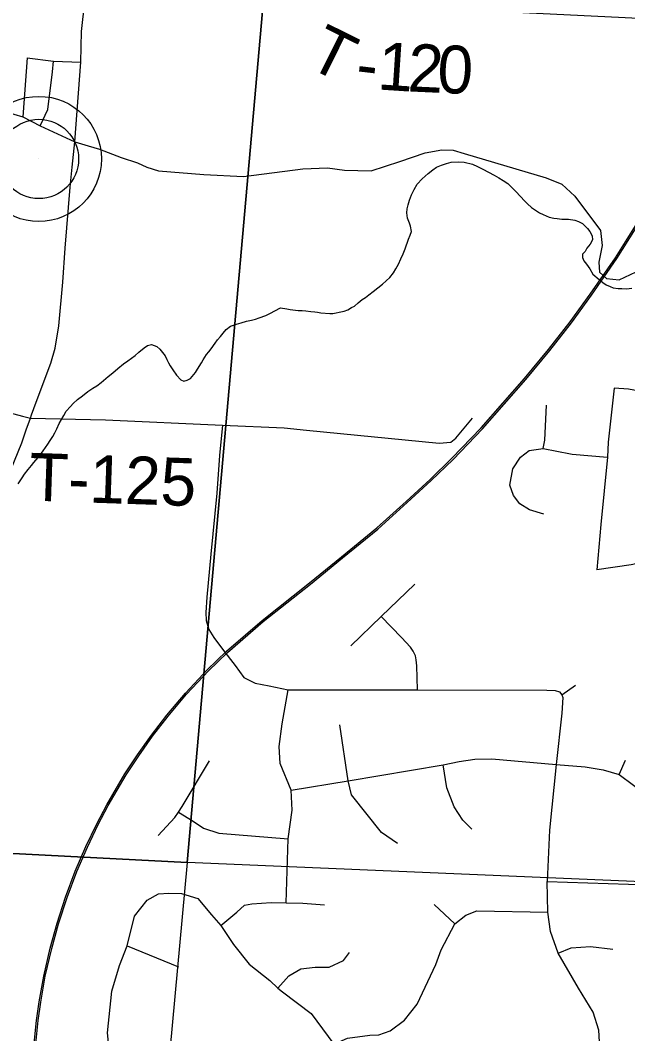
# Model space of a CAD drawing. Extents: x 0 to 34, y 0 to 22.
# Drawn here: x 7.317 to 8.039, y 15.851 to 17.056 of the extents above; entities that cross this region are included whole.
import ezdxf

# ---------------------------------------------------------------- set-up
doc = ezdxf.new("R2010")
doc.units = 0
for name, color, linetype in [('GM_X_County_Road', 7, 'Continuous'), ('GM_X_Minor_River', 7, 'Continuous'), ('GM_X_Rail_Line', 7, 'Continuous'), ('GM_X_Section', 7, 'Continuous'), ('GM_X_Township_Road', 7, 'Continuous'), ('GM_X_Township_Road_Text', 7, 'Continuous'), ('GM_X_Unincorporated', 7, 'Continuous'), ('GM_X_Unincorporated_Location', 7, 'Continuous')]:
    doc.layers.add(name, color=color, linetype=linetype)

msp = doc.modelspace()

# ---------------------------------------------------------------- linework, layer by layer
at = {"layer": 'GM_X_County_Road'}
msp.add_line((7.379, 16.8818), (7.382, 16.9119), dxfattribs=at)
for points in [[(7.382, 16.9119), (7.3892, 17.0066), (7.3899, 17.0431), (7.3983, 17.1175), (7.4035, 17.1411), (7.4162, 17.1655), (7.4386, 17.1904), (7.4667, 17.2146), (7.5042, 17.2448), (7.528, 17.2611), (7.5783, 17.3081), (7.6505, 17.3755), (7.733, 17.4723), (7.8521, 17.6108), (7.8757, 17.6392), (7.9049, 17.673), (7.9181, 17.6858), (7.9702, 17.7222), (8.0096, 17.7756), (8.0113, 17.7781)], [(6.7693, 17.1094), (6.8344, 17.0818), (6.9097, 17.0436), (6.9449, 17.0241), (6.9833, 17.0009), (7.0435, 16.9721), (7.0866, 16.9621), (7.0965, 16.9604), (7.1364, 16.9551), (7.2991, 16.9477), (7.3202, 16.9415), (7.341, 16.9307), (7.382, 16.9119)], [(7.3243, 16.5692), (7.3293, 16.5833), (7.3307, 16.5871), (7.3363, 16.6021), (7.3536, 16.6484), (7.3587, 16.6664), (7.3633, 16.693), (7.3678, 16.745), (7.3705, 16.7852), (7.3767, 16.8577), (7.379, 16.8818)], [(7.2846, 16.4559), (7.2861, 16.4596), (7.3061, 16.5217), (7.319, 16.554), (7.3243, 16.5692)]]:
    msp.add_lwpolyline(points, dxfattribs=at)
at = {"layer": 'GM_X_Minor_River'}
for points in [[(7.7799, 16.8426), (7.7824, 16.8486), (7.7856, 16.855), (7.7892, 16.8613), (7.7951, 16.8676), (7.8021, 16.8742), (7.8076, 16.8783), (7.8122, 16.8815), (7.818, 16.884), (7.8238, 16.8861), (7.8295, 16.8875), (7.8383, 16.888), (7.8451, 16.8874), (7.8549, 16.8852), (7.8609, 16.8823), (7.8673, 16.8791), (7.874, 16.8755), (7.8804, 16.8722), (7.886, 16.869), (7.8912, 16.8658), (7.8968, 16.8622), (7.9064, 16.8528), (7.9119, 16.8469), (7.9167, 16.8415), (7.9204, 16.8379), (7.9249, 16.8336), (7.9308, 16.8296), (7.9346, 16.8272), (7.9387, 16.8252), (7.9424, 16.8236), (7.9458, 16.8223), (7.9515, 16.821), (7.9553, 16.8205), (7.9609, 16.82), (7.9689, 16.8197), (7.9765, 16.8187), (7.981, 16.8171), (7.9855, 16.8147), (7.9914, 16.8088), (7.9943, 16.8053), (7.9972, 16.7999), (7.9975, 16.7953), (7.9947, 16.79), (7.9907, 16.7852), (7.9887, 16.7815), (7.9856, 16.7782), (7.9855, 16.7744), (7.9872, 16.7701), (7.9905, 16.7662), (7.9942, 16.7608), (7.9978, 16.7546), (8.0056, 16.7479), (8.0097, 16.7447), (8.0138, 16.7419), (8.0183, 16.7399), (8.022, 16.7383), (8.0281, 16.7373), (8.0323, 16.7372), (8.038, 16.737), (8.0444, 16.7376)], [(7.3559, 16.5613), (7.3583, 16.5658), (7.3607, 16.5707), (7.3636, 16.5767), (7.3692, 16.5864), (7.372, 16.5916), (7.3771, 16.5972), (7.3802, 16.6005), (7.3853, 16.6053), (7.3911, 16.6097), (7.3977, 16.6148), (7.4036, 16.6188), (7.4082, 16.6217), (7.4136, 16.6257), (7.4218, 16.6327), (7.4273, 16.6371), (7.4331, 16.6422), (7.4398, 16.6477), (7.4452, 16.6514), (7.4537, 16.6579), (7.4584, 16.6616), (7.4646, 16.6667), (7.4685, 16.6697), (7.4731, 16.6707), (7.4795, 16.6686), (7.4832, 16.6654), (7.4865, 16.6611), (7.4894, 16.6572), (7.4916, 16.653), (7.4934, 16.6491), (7.4956, 16.6456), (7.4985, 16.6406), (7.5028, 16.6344), (7.508, 16.6289), (7.5118, 16.6273), (7.5156, 16.6283), (7.5198, 16.6305), (7.5254, 16.6375), (7.5281, 16.6416), (7.5329, 16.6491), (7.5345, 16.6524), (7.5385, 16.6588), (7.5413, 16.6621), (7.544, 16.6658), (7.5488, 16.6725), (7.5516, 16.6762), (7.5551, 16.6803), (7.5583, 16.6844), (7.5622, 16.6888), (7.5673, 16.6925), (7.5745, 16.6949), (7.5799, 16.6967), (7.586, 16.6984), (7.5922, 16.6997), (7.5968, 16.7011), (7.6014, 16.7025), (7.6091, 16.7053), (7.6148, 16.7081), (7.6199, 16.711), (7.6268, 16.7142), (7.634, 16.7133), (7.6381, 16.7124), (7.6476, 16.7113), (7.6522, 16.7112), (7.6567, 16.7107), (7.6628, 16.7101), (7.6673, 16.7096), (7.6707, 16.7091), (7.6745, 16.7086), (7.6851, 16.7075), (7.6889, 16.7078), (7.6928, 16.7084), (7.6962, 16.7091), (7.7023, 16.7104), (7.7066, 16.7122), (7.7112, 16.7147), (7.7147, 16.7165), (7.719, 16.7202), (7.7236, 16.7242), (7.7275, 16.7267), (7.7318, 16.73), (7.7368, 16.7337), (7.7477, 16.7425), (7.7524, 16.7465), (7.7567, 16.7506), (7.7611, 16.7561), (7.7638, 16.7606), (7.7667, 16.7662), (7.7695, 16.7726), (7.7724, 16.7786), (7.7748, 16.7846), (7.7789, 16.7959), (7.7806, 16.8008), (7.7823, 16.8053), (7.7813, 16.8114), (7.7799, 16.8149), (7.7774, 16.821), (7.7768, 16.8275), (7.7773, 16.832), (7.7782, 16.837), (7.7799, 16.8426)], [(7.3147, 16.5052), (7.3195, 16.5123), (7.3223, 16.5167), (7.3266, 16.5223), (7.3306, 16.5271), (7.3333, 16.5305), (7.3384, 16.5364), (7.3412, 16.5401), (7.3444, 16.5442), (7.3499, 16.5524), (7.3527, 16.5565), (7.3559, 16.5613)]]:
    msp.add_lwpolyline(points, dxfattribs=at)
at = {"layer": 'GM_X_Rail_Line'}
for points in [[(7.333, 15.8316), (7.3366, 15.8672), (7.3399, 15.8893), (7.3451, 15.9199), (7.3528, 15.9531), (7.361, 15.9826), (7.371, 16.0138), (7.3827, 16.0447), (7.3953, 16.074), (7.4083, 16.101), (7.4202, 16.1236), (7.4415, 16.1602), (7.4566, 16.183), (7.4731, 16.2062), (7.4915, 16.23), (7.5136, 16.2562), (7.5396, 16.284), (7.5624, 16.3061), (7.605, 16.3428), (7.6609, 16.3875), (7.6992, 16.4185), (7.7412, 16.4529), (7.776, 16.4842), (7.8045, 16.5104), (7.8303, 16.5356), (7.8653, 16.5719), (7.9168, 16.6303), (7.9453, 16.6649), (7.9709, 16.6978), (7.9948, 16.7306), (8.0247, 16.774), (8.0625, 16.834)], [(7.3349, 15.8314), (7.3385, 15.8669), (7.3418, 15.889), (7.347, 15.9196), (7.3547, 15.9526), (7.3628, 15.982), (7.3729, 16.0131), (7.3845, 16.044), (7.397, 16.0732), (7.41, 16.1001), (7.4219, 16.1226), (7.4432, 16.1591), (7.4582, 16.1819), (7.4746, 16.205), (7.493, 16.2288), (7.515, 16.255), (7.541, 16.2827), (7.5637, 16.3047), (7.6062, 16.3413), (7.6622, 16.386), (7.7004, 16.417), (7.7424, 16.4514), (7.7773, 16.4828), (7.8058, 16.509), (7.8317, 16.5342), (7.8667, 16.5706), (7.9183, 16.6291), (7.9468, 16.6637), (7.9724, 16.6966), (7.9964, 16.7295), (8.0263, 16.7729), (8.0641, 16.833)]]:
    msp.add_lwpolyline(points, dxfattribs=at)
at = {"layer": 'GM_X_Section'}
for points in [[(6.5225, 16.4145), (6.585, 17.1294), (7.6063, 17.081), (7.5157, 16.0549), (7.1778, 16.0724)], [(7.1778, 16.0724), (7.5157, 16.0549), (7.4213, 15.0301), (6.4015, 15.0952), (6.4689, 15.8198)]]:
    msp.add_lwpolyline(points, dxfattribs=at)
msp.add_lwpolyline([(8.604, 17.0319), (8.5037, 16.0129), (7.5157, 16.0549), (7.6063, 17.081)], close=True, dxfattribs=at)
at = {"layer": 'GM_X_Township_Road'}
for p, q in [((7.3256, 17.0116), (7.3202, 16.9415)), ((7.9733, 16.5405), (8.0152, 16.5368)), ((7.9611, 16.2542), (7.9772, 16.2659)), ((8.0293, 16.1595), (8.0368, 16.1767)), ((7.8339, 15.9821), (7.8093, 16.0049)), ((7.4445, 15.9558), (7.5055, 15.9309))]:
    msp.add_line(p, q, dxfattribs=at)
for points in [[(7.3256, 17.0116), (7.3569, 17.0078), (7.3892, 17.0066)], [(7.341, 16.9307), (7.3502, 16.9501), (7.3555, 16.995), (7.3569, 17.0078)], [(7.382, 16.9119), (7.3979, 16.907), (7.4113, 16.9029), (7.4374, 16.893), (7.4566, 16.8866), (7.4679, 16.8818), (7.4817, 16.8772), (7.5354, 16.8731), (7.5828, 16.8707), (7.6531, 16.8795), (7.6825, 16.8809), (7.7028, 16.8779), (7.7342, 16.8772), (7.7684, 16.8883), (7.7987, 16.8985), (7.8182, 16.9022), (7.832, 16.902), (7.845, 16.898), (7.9423, 16.8688), (7.9611, 16.8615), (7.9763, 16.847), (8.0069, 16.8062), (8.0088, 16.7884), (8.0052, 16.7685), (8.0058, 16.7568), (8.014, 16.7491), (8.0293, 16.7478), (8.0562, 16.7603)], [(8.0234, 16.6188), (8.0163, 16.5546), (8.0152, 16.5368), (8.0072, 16.4567), (8.0025, 16.4029)], [(8.063, 16.6114), (8.0554, 16.6151), (8.0404, 16.6176), (8.0234, 16.6188)], [(7.103, 16.607), (7.2627, 16.598), (7.2732, 16.5972), (7.2776, 16.5967), (7.2828, 16.5954), (7.2931, 16.5929), (7.3199, 16.5856), (7.3293, 16.5833)], [(7.9387, 16.5473), (7.9407, 16.5572), (7.9427, 16.5985)], [(7.3293, 16.5833), (7.4185, 16.5813), (7.5576, 16.5748), (7.5542, 16.5387), (7.5508, 16.494), (7.5487, 16.4699), (7.5436, 16.4216), (7.5391, 16.3705), (7.5377, 16.3523), (7.5381, 16.3425), (7.5415, 16.332), (7.5472, 16.3225), (7.5578, 16.3086), (7.5729, 16.289), (7.583, 16.2748), (7.5963, 16.2681), (7.613, 16.2649), (7.6358, 16.2603), (7.6388, 16.2603)], [(7.6574, 16.569), (7.8153, 16.5536), (7.8291, 16.5546), (7.8352, 16.5593), (7.8547, 16.5833)], [(7.5576, 16.5748), (7.6308, 16.5717), (7.6574, 16.569)], [(7.9395, 16.4691), (7.9227, 16.4743), (7.9113, 16.4813), (7.9035, 16.4912), (7.8994, 16.5034), (7.9028, 16.5228), (7.912, 16.5367), (7.9224, 16.5447), (7.9387, 16.5473), (7.9712, 16.5407), (7.9733, 16.5405)], [(8.0889, 16.4184), (8.088, 16.4182), (8.0436, 16.4088), (8.0025, 16.4029)], [(7.7102, 16.3125), (7.7463, 16.3473), (7.7861, 16.3857)], [(7.7896, 16.26), (7.7887, 16.2889), (7.7879, 16.2957), (7.7869, 16.3007), (7.7844, 16.306), (7.7811, 16.3108), (7.7705, 16.3223), (7.7463, 16.3473)], [(7.6334, 16.0069), (7.6359, 16.083), (7.6404, 16.117), (7.6394, 16.1409), (7.6264, 16.1724), (7.625, 16.1927), (7.6285, 16.2197), (7.6358, 16.2603)], [(7.6388, 16.2603), (7.7896, 16.26), (7.9434, 16.2596), (7.953, 16.2593), (7.9581, 16.2577), (7.9611, 16.2542), (7.9621, 16.2512), (7.9609, 16.2326), (7.9543, 16.1713), (7.9462, 16.0935), (7.9436, 16.0321), (8.1128, 16.0269), (8.2256, 16.0218), (8.3748, 16.0166), (8.3889, 16.0157), (8.4699, 16.0118), (8.5061, 16.0093), (8.5367, 15.9995), (8.5499, 15.9965), (8.8465, 15.9189), (8.8484, 15.9184), (8.9, 15.906)], [(7.7655, 16.0774), (7.7466, 16.0904), (7.7109, 16.1353), (7.7069, 16.152), (7.6972, 16.2187)], [(7.4813, 16.0869), (7.5009, 16.1083), (7.5052, 16.1147), (7.5097, 16.1216), (7.5423, 16.1756)], [(7.6394, 16.1409), (7.7069, 16.152), (7.8199, 16.1712), (7.8388, 16.175), (7.8576, 16.1778), (7.8777, 16.1783), (7.9543, 16.1713)], [(7.9543, 16.1713), (7.9886, 16.1687), (8.0103, 16.1652), (8.0293, 16.1595), (8.0631, 16.1341), (8.0765, 16.1241), (8.0929, 16.1177), (8.1094, 16.1156), (8.1383, 16.1158), (8.2286, 16.109), (8.3078, 16.1059), (8.3815, 16.103), (8.3885, 16.1028), (8.5068, 16.0962), (8.5555, 16.0835), (8.5696, 16.0798), (8.8164, 16.0206), (8.8677, 16.0074), (8.8988, 16.0028), (8.9, 16.0027)], [(7.8542, 16.0944), (7.8435, 16.1053), (7.8329, 16.121), (7.8242, 16.1437), (7.8199, 16.1712)], [(7.5052, 16.1147), (7.5227, 16.1041), (7.5349, 16.0956), (7.5535, 16.0897), (7.6359, 16.083)], [(8.0063, 15.8344), (8.0049, 15.8555), (7.9982, 15.8768), (7.9807, 15.9056), (7.9565, 15.947), (7.9474, 15.9729), (7.9443, 15.9957), (7.9436, 16.0321)], [(7.4205, 15.4776), (7.446, 15.7123), (7.442, 15.7492), (7.4336, 15.7815), (7.4242, 15.8219), (7.421, 15.8523), (7.426, 15.9018), (7.4351, 15.9323), (7.4445, 15.9558), (7.4532, 15.991), (7.468, 16.01), (7.4817, 16.0175), (7.4939, 16.0184), (7.509, 16.0182), (7.5282, 16.0121), (7.5444, 15.9926), (7.5555, 15.98), (7.5707, 15.9575), (7.5893, 15.934), (7.6138, 15.9146), (7.6236, 15.9053), (7.629, 15.9012), (7.6629, 15.8752), (7.6902, 15.8387)], [(7.5555, 15.98), (7.5749, 15.996), (7.584, 16.0042), (7.5926, 16.0059), (7.6157, 16.0072), (7.6334, 16.0069), (7.6531, 16.0066), (7.679, 16.0045)], [(7.6198, 15.74), (7.6457, 15.7795), (7.6657, 15.8096), (7.68, 15.8261), (7.6902, 15.8387), (7.7063, 15.8461), (7.7329, 15.8496), (7.7435, 15.8499), (7.7571, 15.8548), (7.774, 15.8674), (7.789, 15.8864), (7.8111, 15.9337), (7.8174, 15.9509), (7.8339, 15.9821), (7.8468, 15.9922), (7.8598, 15.9975), (7.9443, 15.9957)], [(7.9565, 15.947), (7.9723, 15.9534), (7.995, 15.9552), (8.0217, 15.9517)], [(7.6236, 15.9053), (7.6364, 15.92), (7.6506, 15.9285), (7.6678, 15.9305), (7.6846, 15.9305), (7.7015, 15.9383), (7.7088, 15.9477)]]:
    msp.add_lwpolyline(points, dxfattribs=at)
at = {"layer": 'GM_X_Unincorporated'}
for radius in [0.0744, 0.0472]:
    msp.add_circle((7.3394, 16.8914), radius, dxfattribs=at)
at = {"layer": 'GM_X_Unincorporated_Location'}
msp.add_line((7.3394, 16.8914), (7.3394, 16.8914), dxfattribs=at)

# ---------------------------------------------------------------- texts
at = {"layer": 'GM_X_Township_Road_Text'}
for s, height, rotation, p in [('T', 0.0568, 333.6046, (7.6561, 17.0021)), ('1', 0.0568, 356.2852, (7.7409, 16.9741)), ('2', 0.0568, 357.3682, (7.777, 16.9718)), ('0', 0.0568, 357.665, (7.8122, 16.9702)), ('-', 0.0568, 353.2445, (7.7144, 16.9772)), ('T-125', 0.05682, 358.0445, (7.3271, 16.4853))]:
    msp.add_text(s, height=height, rotation=rotation, dxfattribs=at).set_placement(p)

doc.saveas('drawing.dxf')
